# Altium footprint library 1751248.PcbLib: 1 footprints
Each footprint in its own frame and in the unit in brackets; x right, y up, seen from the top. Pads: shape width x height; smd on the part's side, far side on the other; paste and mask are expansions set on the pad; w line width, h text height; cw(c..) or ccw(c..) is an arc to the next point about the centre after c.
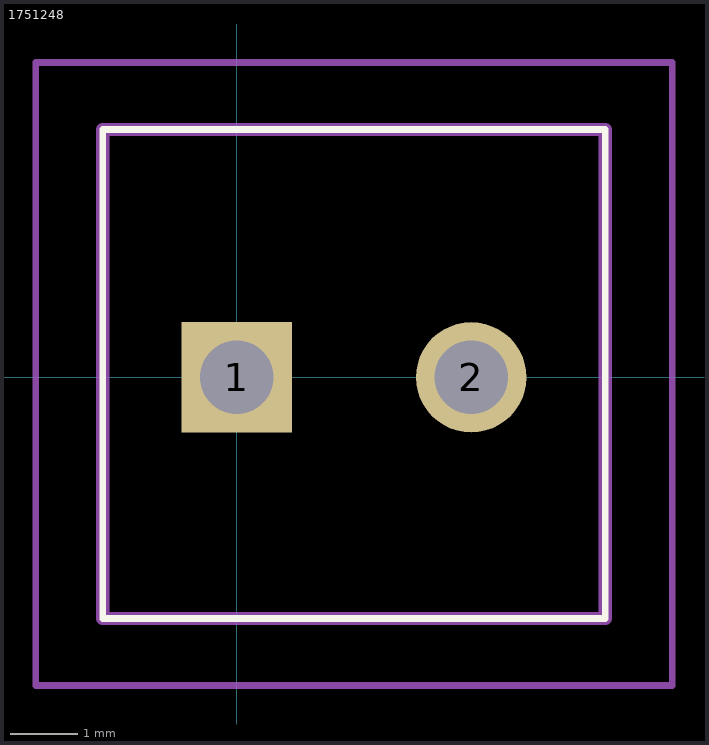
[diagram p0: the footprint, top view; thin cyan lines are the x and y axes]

## 1751248 [mm]
pads (2):
  rect 1.65x1.65 hole 1.1: 1(0,0)
  round 1.65 hole 1.1: 2(3.5,0)
Top Overlay:
  lines w0.1: -2,-3.6 5.5,-3.6 5.5,3.7 -2,3.7 -2,-3.6
Mechanical 15:
  lines w0.2: -2,-3.6 5.5,-3.6 5.5,3.7 -2,3.7 -2,-3.6
Mechanical 20:
  lines w0.1: -3,-4.6 6.5,-4.6 6.5,4.7 -3,4.7 -3,-4.6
